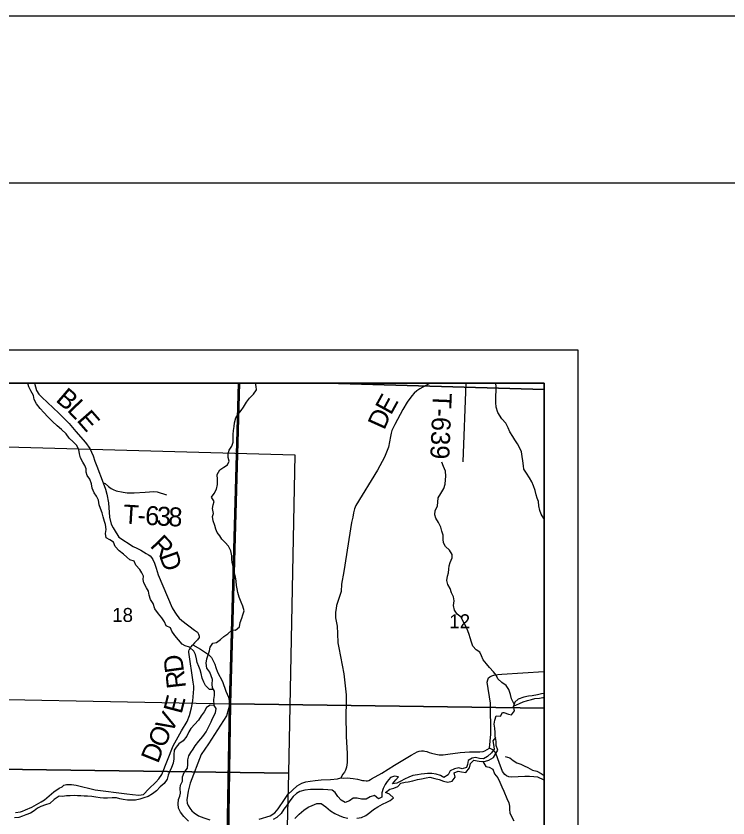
# Model space of a CAD drawing. Extents: x -19.9 to 41.9, y 0 to 32.3.
# Drawn here: x 7.317 to 9.45, y 19.598 to 22 of the extents above; entities that cross this region are included whole.
import ezdxf

# ---------------------------------------------------------------- set-up
doc = ezdxf.new("R2010")
doc.units = 0
for name, color, linetype in [('GM_X_Corporation', 7, 'Continuous'), ('GM_X_County_Road', 7, 'Continuous'), ('GM_X_County_Road_Text', 7, 'Continuous'), ('GM_X_Major_Lake', 7, 'Continuous'), ('GM_X_Major_River', 7, 'Continuous'), ('GM_X_Minor_River', 7, 'Continuous'), ('GM_X_Section', 7, 'Continuous'), ('GM_X_Section_Text', 7, 'Continuous'), ('GM_X_Township_Road', 7, 'Continuous'), ('GM_X_Township_Road_Text', 7, 'Continuous'), ('SH_Border', 7, 'Continuous'), ('SH_Cut_Line', 7, 'Continuous'), ('SH_Data', 7, 'Continuous')]:
    doc.layers.add(name, color=color, linetype=linetype)

msp = doc.modelspace()

# ---------------------------------------------------------------- linework, layer by layer
at = {"layer": 'GM_X_Corporation'}
for points in [[(8.9, 17.8974), (8.9, 20.9), (2.1, 20.9), (2.1, 17.918), (2.4715, 17.9106), (2.973, 17.9007), (3.7505, 17.884), (3.984, 17.879), (4.2613, 17.8672), (4.9169, 17.8392), (5.0192, 17.8403), (5.0257, 17.9637), (5.4954, 17.9559), (5.761, 17.9543), (5.9048, 17.9534), (6.2397, 17.9517), (6.2497, 17.9517), (6.3069, 17.9505), (6.7, 17.9422), (6.9468, 17.937), (7.3858, 17.9277), (7.5529, 17.9242), (7.9072, 17.9171)], [(7.9862, 20.9), (6.9594, 20.9), (6.9305, 19.9596), (7.9591, 19.9393)], [(8.9, 17.8974), (8.9, 20.9), (7.9833, 20.9), (7.9567, 19.9408), (7.9433, 19.1981), (7.9387, 18.9418), (7.9208, 18.3004), (7.9072, 17.9171)], [(8.2492, 20.9), (7.9862, 20.9), (7.9591, 19.9393), (8.9, 19.9267), (8.9, 20.8818)], [(8.9, 20.8818), (8.9, 20.9), (8.2492, 20.9)], [(7.9591, 19.9393), (7.944, 18.9426), (6.9135, 18.9637), (6.9305, 19.9596)], [(8.9, 18.9209), (8.9, 19.9267), (7.9591, 19.9393), (7.944, 18.9426)]]:
    msp.add_lwpolyline(points, close=True, dxfattribs=at)
msp.add_lwpolyline([(2.973, 17.9007), (3.7505, 17.884), (3.984, 17.879), (4.2613, 17.8672), (4.9169, 17.8392), (5.0192, 17.8403), (5.0257, 17.9637), (5.4954, 17.9559), (5.761, 17.9543), (5.9048, 17.9534), (6.2397, 17.9517), (6.2497, 17.9517), (6.3069, 17.9505), (6.7, 17.9422), (6.9468, 17.937), (7.3858, 17.9277), (7.5529, 17.9242), (7.9072, 17.9171), (7.9208, 18.3004), (7.9387, 18.9418), (7.9433, 19.1981), (7.9567, 19.9408), (7.9833, 20.9), (2.1, 20.9)], dxfattribs=at)
at = {"layer": 'GM_X_County_Road'}
for points in [[(7.3718, 20.9), (7.3775, 20.8787), (7.3846, 20.8678), (7.3944, 20.858), (7.4453, 20.8106), (7.4758, 20.7798), (7.4959, 20.7553), (7.5246, 20.7225), (7.5377, 20.7041), (7.5478, 20.6822), (7.5526, 20.667), (7.5588, 20.6514), (7.5775, 20.6016), (7.5849, 20.5825), (7.5887, 20.5678), (7.5933, 20.5419), (7.5968, 20.4993), (7.6017, 20.4776), (7.6074, 20.467), (7.6103, 20.4616), (7.6248, 20.4392), (7.668, 20.4112), (7.6784, 20.4056), (7.6911, 20.4005), (7.7069, 20.3901), (7.7141, 20.3861), (7.7182, 20.3827), (7.7225, 20.3783), (7.7268, 20.3718), (7.7321, 20.3615), (7.7366, 20.3457), (7.7423, 20.326), (7.7848, 20.2276), (7.7923, 20.2145), (7.7985, 20.2054), (7.8051, 20.1959), (7.8132, 20.1897), (7.8515, 20.1605), (7.8604, 20.1545), (7.8637, 20.1486), (7.8653, 20.1427), (7.8651, 20.1381), (7.8609, 20.1311), (7.852, 20.122)], [(7.852, 20.122), (7.8465, 20.1165), (7.8692, 20.1036), (7.8931, 20.0875), (7.9023, 20.0787), (7.9069, 20.0707), (7.9124, 20.0582), (7.9159, 20.0482), (7.9208, 20.0351), (7.9352, 20.0063), (7.9453, 19.9779), (7.9532, 19.9599), (7.9571, 19.9396), (7.9538, 19.9248), (7.9476, 19.9042), (7.8933, 19.8198), (7.8717, 19.7877), (7.8386, 19.7026), (7.8323, 19.6777), (7.829, 19.652), (7.8299, 19.6427), (7.8329, 19.635), (7.8373, 19.6271), (7.8437, 19.6191), (7.8507, 19.6128), (7.8632, 19.6045), (7.8792, 19.5982), (7.8977, 19.5919)], [(8.2899, 19.718), (8.2988, 19.7174), (8.3095, 19.7183), (8.3267, 19.7163), (8.3404, 19.7141), (8.3546, 19.7101), (8.3605, 19.7097), (8.3656, 19.7095), (8.3702, 19.7095), (8.3742, 19.7104), (8.3793, 19.7128), (8.3825, 19.7153), (8.4127, 19.7321), (8.451, 19.7557), (8.501, 19.7863), (8.5123, 19.7922), (8.5188, 19.796), (8.5252, 19.7984), (8.5319, 19.7992), (8.538, 19.7988), (8.5423, 19.798), (8.5477, 19.7967), (8.5548, 19.7939), (8.562, 19.7923), (8.5752, 19.7888), (8.5848, 19.7872), (8.5969, 19.7866), (8.6109, 19.7885), (8.6474, 19.7944), (8.6756, 19.796), (8.6965, 19.7963), (8.7072, 19.796), (8.7166, 19.7968), (8.722, 19.7989), (8.7359, 19.8073), (8.74, 19.8494), (8.7385, 19.9414), (8.729, 20.0043), (8.7302, 20.0112), (8.733, 20.0172), (8.7365, 20.0208), (8.7422, 20.0236), (8.7491, 20.0255), (8.7603, 20.0279), (8.7727, 20.0287), (8.8989, 20.0362), (8.9, 20.0363)], [(8.0453, 19.5943), (8.0783, 19.604), (8.0923, 19.6128), (8.1027, 19.6253), (8.1212, 19.6535), (8.1315, 19.6685), (8.1591, 19.6937), (8.1733, 19.7017), (8.1849, 19.7057), (8.1982, 19.7083), (8.2128, 19.7103), (8.2316, 19.7122), (8.2593, 19.7129), (8.28, 19.7156), (8.2899, 19.718)]]:
    msp.add_lwpolyline(points, dxfattribs=at)
at = {"layer": 'GM_X_Major_Lake'}
for points in [[(7.8022, 19.6402), (7.8039, 19.6531), (7.8075, 19.6627), (7.8093, 19.6722), (7.809, 19.6858), (7.81, 19.6957), (7.8159, 19.7083), (7.816, 19.7216), (7.8208, 19.7342), (7.8308, 19.7473), (7.8318, 19.7583), (7.8312, 19.7719), (7.8348, 19.7841), (7.8407, 19.7937), (7.8474, 19.8041), (7.854, 19.814), (7.8648, 19.8275), (7.8764, 19.8417), (7.886, 19.8555), (7.8912, 19.8655), (7.8963, 19.8758), (7.9019, 19.8862), (7.9059, 19.8961), (7.9143, 19.9133), (7.9168, 19.9255), (7.9102, 19.9352), (7.898, 19.9354), (7.8875, 19.9284), (7.8805, 19.9158), (7.8715, 19.9035), (7.8638, 19.8905), (7.8406, 19.8658), (7.8343, 19.8558), (7.8281, 19.8432), (7.8177, 19.8294), (7.8049, 19.82), (7.7963, 19.8104), (7.7904, 19.8008), (7.7891, 19.7868), (7.7893, 19.7746), (7.7872, 19.7617), (7.7829, 19.7487), (7.7763, 19.7361), (7.7726, 19.7262), (7.7698, 19.714), (7.7605, 19.7013), (7.7489, 19.6916), (7.7381, 19.6789), (7.7253, 19.67), (7.7125, 19.6618), (7.7, 19.6578), (7.6879, 19.6542), (7.675, 19.6517), (7.6511, 19.6513), (7.6381, 19.6534), (7.6282, 19.6555), (7.6179, 19.658), (7.605, 19.6585), (7.5909, 19.6575), (7.5791, 19.6573), (7.5689, 19.6579), (7.5563, 19.66), (7.5437, 19.6617), (7.5311, 19.663), (7.5213, 19.6636), (7.511, 19.6645), (7.5011, 19.6644), (7.4904, 19.6649), (7.479, 19.6644), (7.468, 19.6638), (7.4559, 19.6625), (7.4464, 19.6627), (7.4306, 19.6533), (7.4175, 19.6413), (7.4046, 19.6373), (7.3914, 19.6326), (7.3808, 19.6274), (7.3707, 19.6197), (7.3602, 19.6127), (7.3462, 19.6068), (7.3364, 19.6036), (7.3246, 19.5996), (7.3125, 19.5986)], [(8.3385, 19.5968), (8.3522, 19.5993), (8.3646, 19.6048), (8.3774, 19.6145), (8.3883, 19.6231), (8.4014, 19.6309), (8.4154, 19.6394), (8.4278, 19.6457), (8.4376, 19.6501), (8.4481, 19.6586), (8.4358, 19.6694), (8.4235, 19.6737), (8.4367, 19.6846), (8.4492, 19.6867), (8.4612, 19.6926), (8.4702, 19.7026), (8.4827, 19.7051), (8.4922, 19.706), (8.5058, 19.7092), (8.5198, 19.7129), (8.5319, 19.7154), (8.5459, 19.7186), (8.5573, 19.72), (8.5718, 19.716), (8.5852, 19.7132), (8.5982, 19.7085), (8.6108, 19.7049), (8.624, 19.7086), (8.633, 19.7197), (8.6297, 19.7326), (8.6422, 19.7385), (8.6517, 19.736), (8.6647, 19.7343), (8.6755, 19.7477), (8.6783, 19.7611), (8.6891, 19.7711), (8.6987, 19.769), (8.7109, 19.7669), (8.7234, 19.7683), (8.7332, 19.7715), (8.7475, 19.7789), (8.7549, 19.7912), (8.7605, 19.8008), (8.7561, 19.8147), (8.7555, 19.8268), (8.7538, 19.839)], [(8.7538, 19.839), (8.746, 19.829), (8.7473, 19.8176), (8.7498, 19.804), (8.7412, 19.7932), (8.7296, 19.782), (8.718, 19.775), (8.7058, 19.7763), (8.6939, 19.7792), (8.6833, 19.7775), (8.672, 19.7704), (8.67, 19.7583), (8.6663, 19.7487), (8.6535, 19.7451), (8.6439, 19.7476), (8.6306, 19.7455), (8.6182, 19.7392), (8.6116, 19.7266), (8.5988, 19.7191), (8.5884, 19.7247), (8.5754, 19.729), (8.5625, 19.7314), (8.5503, 19.7309), (8.5408, 19.7296), (8.5306, 19.7286), (8.5203, 19.7273)], [(8.4701, 19.7083), (8.4576, 19.7024), (8.4448, 19.7006), (8.4548, 19.7118), (8.4626, 19.7214), (8.4512, 19.7235), (8.4391, 19.7187), (8.4294, 19.7076), (8.4231, 19.698), (8.4169, 19.6858), (8.4125, 19.6728), (8.4127, 19.6603), (8.4025, 19.6555), (8.391, 19.6656), (8.3781, 19.6608), (8.3657, 19.6542), (8.3524, 19.6547), (8.3394, 19.6571), (8.3269, 19.6569), (8.3164, 19.6496), (8.3035, 19.644), (8.2916, 19.651), (8.2815, 19.6626), (8.2734, 19.6739), (8.2638, 19.6813), (8.2508, 19.6818), (8.2371, 19.6831), (8.2257, 19.6833), (8.2128, 19.6835), (8.1995, 19.6829), (8.1824, 19.6815), (8.1676, 19.6774), (8.1575, 19.6708), (8.1477, 19.6623), (8.1369, 19.6492), (8.1269, 19.6342), (8.1195, 19.6239), (8.111, 19.6116), (8.0982, 19.5992), (8.0869, 19.5937)], [(8.5203, 19.7273), (8.5063, 19.7248), (8.4938, 19.7204), (8.481, 19.7145), (8.4701, 19.7083)], [(7.8331, 19.5887), (7.8199, 19.6018), (7.8091, 19.6153), (7.8039, 19.6277), (7.8022, 19.6402)], [(8.1519, 19.5963), (8.1657, 19.6095), (8.1788, 19.6215), (8.192, 19.63), (8.2037, 19.6348), (8.2177, 19.6415), (8.231, 19.6409), (8.2452, 19.6309), (8.2587, 19.619), (8.2725, 19.6113), (8.2848, 19.605), (8.2974, 19.6007), (8.3111, 19.5971)]]:
    msp.add_lwpolyline(points, dxfattribs=at)
at = {"layer": 'GM_X_Major_River'}
for points in [[(8.9, 19.9703), (8.8911, 19.9694), (8.8791, 19.9665), (8.8636, 19.9638), (8.853, 19.9629), (8.8383, 19.9599), (8.8217, 19.9542), (8.8117, 19.9446), (8.8078, 19.9323)], [(8.8078, 19.9323), (8.8254, 19.9406), (8.8361, 19.9458), (8.8498, 19.9498), (8.8618, 19.9523), (8.8716, 19.9559), (8.8855, 19.9569), (8.8957, 19.9586), (8.9, 19.959)], [(8.7538, 19.839), (8.7522, 19.8408), (8.7528, 19.8537), (8.7518, 19.867), (8.7497, 19.8787), (8.7514, 19.8909), (8.7557, 19.9035), (8.769, 19.9033), (8.7749, 19.9137)], [(8.7749, 19.9137), (8.779, 19.9135), (8.7924, 19.9085), (8.8019, 19.9072), (8.8111, 19.9188), (8.8078, 19.9323)]]:
    msp.add_lwpolyline(points, dxfattribs=at)
at = {"layer": 'GM_X_Minor_River'}
for points in [[(7.9082, 19.983), (7.8967, 19.9826), (7.8848, 19.9947), (7.8791, 20.0045), (7.8744, 20.0166), (7.8716, 20.0302), (7.8685, 20.0419), (7.8646, 20.0518), (7.8599, 20.0635), (7.8572, 20.0741), (7.8544, 20.0873), (7.8494, 20.0979), (7.8367, 20.1092), (7.8238, 20.1136), (7.8142, 20.1185), (7.8035, 20.1313), (7.7927, 20.1448), (7.7839, 20.1573), (7.7792, 20.1675), (7.7667, 20.1731), (7.7612, 20.1855), (7.7535, 20.1972), (7.7432, 20.2093), (7.7328, 20.224), (7.7273, 20.2402), (7.72, 20.2527), (7.7161, 20.2652), (7.7137, 20.2773), (7.7075, 20.2871), (7.6994, 20.3018), (7.6974, 20.3117), (7.6985, 20.3219), (7.6939, 20.3318), (7.6873, 20.3423), (7.6758, 20.3551), (7.6708, 20.3672), (7.6582, 20.3709), (7.6486, 20.3792), (7.639, 20.3882), (7.626, 20.3983), (7.6138, 20.4107), (7.6087, 20.424), (7.598, 20.4311), (7.587, 20.4367), (7.5849, 20.4499), (7.5867, 20.4617), (7.5843, 20.4765), (7.5816, 20.4863), (7.5773, 20.4996), (7.5745, 20.512), (7.5698, 20.5245), (7.5659, 20.5355), (7.5635, 20.5495), (7.5577, 20.562), (7.5504, 20.5718), (7.5446, 20.5854), (7.5426, 20.599), (7.5383, 20.6123), (7.5298, 20.6236), (7.5267, 20.6334), (7.5266, 20.6433), (7.5224, 20.6535), (7.5166, 20.664), (7.51, 20.6765), (7.5072, 20.689), (7.5052, 20.7019), (7.4983, 20.7147), (7.4879, 20.7245), (7.4757, 20.7354), (7.4668, 20.7486), (7.4534, 20.7617), (7.4404, 20.7726), (7.4262, 20.7858), (7.4121, 20.7997), (7.3998, 20.8121), (7.3887, 20.8245), (7.3783, 20.8385), (7.3706, 20.8517), (7.3686, 20.8638), (7.3612, 20.8778), (7.3554, 20.8891), (7.3522, 20.9)], [(7.9102, 19.9352), (7.9091, 19.9531), (7.9113, 19.9649), (7.9116, 19.9778), (7.905, 19.988), (7.9049, 19.9986), (7.9052, 20.013), (7.9013, 20.0232), (7.8974, 20.0342), (7.8889, 20.047), (7.8862, 20.0611), (7.8883, 20.0747), (7.8928, 20.0861), (7.8961, 20.0987), (7.8986, 20.1093), (7.9069, 20.1212), (7.9171, 20.1232), (7.9292, 20.1327), (7.9398, 20.1419), (7.9519, 20.1496), (7.9647, 20.1611), (7.9745, 20.1604), (7.9859, 20.1708), (7.9884, 20.1837), (7.9932, 20.1966), (7.9965, 20.2065), (7.9999, 20.2187), (7.9959, 20.2327), (7.9909, 20.2448), (7.9855, 20.2592), (7.9812, 20.2728), (7.9792, 20.2842), (7.9779, 20.294), (7.9767, 20.3073), (7.9743, 20.3201), (7.9703, 20.336), (7.968, 20.3482), (7.9648, 20.3629), (7.9632, 20.3732), (7.9638, 20.3826), (7.9607, 20.3982), (7.953, 20.4118), (7.943, 20.4227), (7.9338, 20.4332), (7.9272, 20.443), (7.9199, 20.4532), (7.9157, 20.4634), (7.9121, 20.4736), (7.9075, 20.4884), (7.9058, 20.5005), (7.9084, 20.51), (7.9056, 20.5248), (7.907, 20.5354), (7.9104, 20.5461), (7.9023, 20.5589), (7.9109, 20.57), (7.9176, 20.5825), (7.9206, 20.597), (7.92, 20.6121), (7.9199, 20.6266), (7.927, 20.6403), (7.9398, 20.6491), (7.9508, 20.656), (7.9556, 20.6667), (7.9529, 20.6781), (7.9524, 20.6891), (7.9553, 20.7001), (7.9636, 20.7115), (7.9673, 20.7237), (7.9676, 20.7366), (7.9679, 20.7461), (7.9681, 20.759), (7.9707, 20.77), (7.9717, 20.781), (7.9758, 20.7962), (7.9833, 20.8088), (7.9911, 20.8187), (7.9986, 20.8287), (8.0069, 20.8435), (8.0166, 20.855), (8.0287, 20.8676), (8.0377, 20.8806), (8.0361, 20.8901), (8.0344, 20.9)], [(8.7604, 20.8121), (8.7553, 20.8288), (8.7544, 20.8424), (8.7543, 20.8549), (8.755, 20.8648), (8.756, 20.8754), (8.7559, 20.8895), (8.7547, 20.9)], [(8.9, 20.4933), (8.8982, 20.4954), (8.8908, 20.5077), (8.8868, 20.5187), (8.8839, 20.533), (8.8822, 20.5455), (8.879, 20.5557), (8.8754, 20.5658), (8.8725, 20.5787), (8.8678, 20.5923), (8.8622, 20.6047), (8.8556, 20.6171), (8.8466, 20.6309), (8.8389, 20.6429), (8.8372, 20.6528), (8.8358, 20.6675), (8.8337, 20.6811), (8.8315, 20.6944), (8.8256, 20.7075), (8.8201, 20.7188), (8.8112, 20.7308), (8.8061, 20.7405), (8.7968, 20.7544), (8.7917, 20.7668), (8.7843, 20.7803), (8.7727, 20.793), (8.7604, 20.8121)], [(8.7728, 20.0039), (8.7606, 20.0151), (8.7555, 20.0257), (8.7475, 20.0359), (8.7356, 20.0491), (8.7271, 20.0592), (8.7168, 20.072), (8.7117, 20.0838), (8.7063, 20.0947), (8.696, 20.1011), (8.686, 20.1127), (8.6814, 20.1248), (8.6778, 20.1373), (8.6751, 20.1472), (8.6712, 20.1585), (8.6661, 20.1706), (8.6573, 20.1846), (8.6507, 20.1997), (8.6392, 20.2087), (8.6304, 20.2208), (8.6276, 20.2348), (8.6298, 20.2481), (8.6277, 20.2602), (8.6216, 20.2719), (8.6176, 20.2851), (8.6111, 20.2972), (8.6079, 20.3089), (8.6101, 20.3222), (8.6127, 20.3317), (8.6137, 20.3431), (8.6148, 20.3534), (8.6173, 20.3629), (8.6237, 20.3766), (8.624, 20.3868), (8.6159, 20.4001), (8.604, 20.4106), (8.5978, 20.4223), (8.5966, 20.4329), (8.5965, 20.4454), (8.5933, 20.4568), (8.5898, 20.4693), (8.5825, 20.4832), (8.5744, 20.4957), (8.572, 20.5059), (8.573, 20.5192), (8.5798, 20.5321), (8.5818, 20.5572), (8.5901, 20.5702), (8.5991, 20.5843), (8.6027, 20.5976), (8.6034, 20.6109), (8.6048, 20.6215), (8.6043, 20.6367), (8.5981, 20.6503), (8.593, 20.6639)], [(8.8098, 19.9386), (8.8015, 19.9551), (8.7987, 19.9679), (8.7935, 19.9826), (8.7853, 19.995), (8.7728, 20.0039)], [(8.7829, 19.7823), (8.7963, 19.7776), (8.807, 19.7698), (8.8177, 19.7635), (8.8292, 19.7588), (8.8398, 19.754), (8.8509, 19.7493), (8.8647, 19.7412), (8.878, 19.7376), (8.891, 19.731), (8.9, 19.7253)], [(8.716, 19.7675), (8.7249, 19.7523), (8.7344, 19.7497), (8.7455, 19.7438), (8.7505, 19.7305), (8.7605, 19.7177), (8.7667, 19.7056), (8.7729, 19.6909), (8.7783, 19.678)], [(8.7783, 19.678), (8.7874, 19.6565), (8.7937, 19.6433), (8.7957, 19.6335), (8.7959, 19.6233), (8.7968, 19.6134), (8.8031, 19.5999), (8.8082, 19.5893)]]:
    msp.add_lwpolyline(points, dxfattribs=at)
at = {"layer": 'GM_X_Section'}
for points in [[(7.1444, 20.7139), (8.1526, 20.6857), (8.1335, 19.7322), (7.1171, 19.7458)], [(7.1171, 19.7458), (8.1335, 19.7322), (8.1079, 18.7263), (7.1021, 18.7492)]]:
    msp.add_lwpolyline(points, close=True, dxfattribs=at)
at = {"layer": 'GM_X_Township_Road'}
msp.add_line((8.665, 20.9), (8.6553, 20.6648), dxfattribs=at)
for points in [[(8.5566, 20.9), (8.5559, 20.8996), (8.5269, 20.8834), (8.5177, 20.8776), (8.5096, 20.8708), (8.5026, 20.8626), (8.4892, 20.8434), (8.4756, 20.8214), (8.4523, 20.7764), (8.4481, 20.7685), (8.4432, 20.7581), (8.4422, 20.7541)], [(8.4422, 20.7541), (8.4411, 20.7502), (8.4389, 20.7406), (8.4359, 20.7248), (8.4327, 20.7085), (8.4209, 20.6785), (8.4003, 20.6398), (8.3352, 20.534), (8.3313, 20.5241), (8.3279, 20.5119), (8.326, 20.4994), (8.3223, 20.4832), (8.2991, 20.3365), (8.2926, 20.2985), (8.291, 20.2758), (8.2773, 20.2346), (8.2757, 20.2257), (8.2744, 20.2142), (8.2744, 20.1976), (8.2788, 20.1723), (8.2805, 20.1505), (8.2815, 20.1229), (8.2845, 20.1071), (8.2995, 20.0298), (8.3059, 19.9669), (8.3065, 19.9415), (8.305, 19.9068), (8.3062, 19.8421), (8.3088, 19.7914), (8.309, 19.7638), (8.3073, 19.7501), (8.304, 19.7414), (8.3006, 19.7353), (8.2957, 19.7289), (8.2899, 19.718)], [(7.5775, 20.6016), (7.5835, 20.5993), (7.5934, 20.5909), (7.6015, 20.5843), (7.6075, 20.5816), (7.6169, 20.5781), (7.6381, 20.5737), (7.6502, 20.5723), (7.6702, 20.5721), (7.7032, 20.5742), (7.7166, 20.575), (7.7287, 20.5755), (7.7398, 20.5745), (7.7677, 20.5659)], [(7.315, 19.6147), (7.3299, 19.6167), (7.3357, 19.6187), (7.3451, 19.6224), (7.3643, 19.6306), (7.3919, 19.6459), (7.402, 19.6518), (7.4302, 19.6766), (7.4455, 19.687), (7.4547, 19.6915), (7.4598, 19.6964), (7.4682, 19.6985), (7.4832, 19.6985), (7.4972, 19.6964), (7.5537, 19.6817), (7.6486, 19.6702), (7.6654, 19.6681), (7.6851, 19.6666), (7.6982, 19.6685), (7.7143, 19.6851), (7.7356, 19.7052), (7.7446, 19.7149), (7.7539, 19.7283), (7.7874, 19.8144), (7.8122, 19.8593), (7.8292, 19.887), (7.8369, 19.9046), (7.843, 19.9279), (7.8464, 19.9484), (7.8491, 19.9848), (7.8491, 19.9922), (7.8477, 20.0043), (7.8345, 20.0947), (7.8346, 20.0979), (7.8356, 20.1012), (7.8365, 20.1029), (7.8405, 20.1098), (7.8465, 20.1165)], [(8.9, 19.7107), (8.8803, 19.7197), (8.8688, 19.7216), (8.8558, 19.7222), (8.842, 19.7226), (8.8018, 19.72), (8.7932, 19.7214), (8.7864, 19.7243), (8.7814, 19.7282), (8.7748, 19.7368), (8.7644, 19.7643), (8.7557, 19.7893), (8.7517, 19.7955), (8.7454, 19.8015), (8.7359, 19.8073)]]:
    msp.add_lwpolyline(points, dxfattribs=at)
at = {"layer": 'SH_Border'}
msp.add_lwpolyline([(1.5, 21.5), (33.5, 21.5), (33.5, 0.5), (1.5, 0.5)], close=True, dxfattribs=at)
at = {"layer": 'SH_Cut_Line'}
msp.add_lwpolyline([(0, 0), (34, 0), (34, 22), (0, 22)], close=True, dxfattribs=at)
at = {"layer": 'SH_Data'}
for p, q in [((2, 21), (9, 21)), ((9, 21), (9, 14)), ((2.1, 20.9), (8.9, 20.9)), ((8.9, 20.9), (8.9, 14.1))]:
    msp.add_line(p, q, dxfattribs=at)

# ---------------------------------------------------------------- texts
at = {"layer": 'GM_X_County_Road_Text'}
for s, rotation, p in [('B', 319.314, (7.4329, 20.8478)), ('L', 314.25, (7.4673, 20.8183)), ('E', 311.1577, (7.4964, 20.7884)), ('R', 314.1265, (7.7161, 20.4116)), ('D', 289.4522, (7.7452, 20.3836))]:
    msp.add_text(s, height=0.0568, rotation=rotation, dxfattribs=at).set_placement(p)
at = {"layer": 'GM_X_Section_Text'}
for s, p in [('18', (7.6049, 20.185)), ('12', (8.6153, 20.1662))]:
    msp.add_text(s, height=0.04186, rotation=0, dxfattribs=at).set_placement(p)
at = {"layer": 'GM_X_Township_Road_Text'}
for s, height, rotation, p in [('E', 0.0568, 61.2715, (8.4403, 20.8024)), ('T-639', 0.05682, 267.6418, (8.5662, 20.8718)), ('D', 0.0568, 65.7619, (8.4202, 20.7578)), ('T', 0.0568, 356.4347, (7.6366, 20.4803)), ('6', 0.0568, 356.8827, (7.7025, 20.4763)), ('3', 0.0568, 356.8927, (7.7372, 20.4744)), ('8', 0.0568, 356.8927, (7.7718, 20.4726)), ('-', 0.0568, 356.8312, (7.6793, 20.4776)), ('D', 0.0568, 97.8658, (7.8206, 20.0365)), ('R', 0.0568, 96.4985, (7.8261, 19.9887)), ('E', 0.0568, 75.395, (7.8126, 19.9074)), ('V', 0.0568, 59.6985, (7.7809, 19.8486)), ('O', 0.0568, 64.6789, (7.7602, 19.8045)), ('D', 0.0568, 68.2513, (7.742, 19.7589))]:
    msp.add_text(s, height=height, rotation=rotation, dxfattribs=at).set_placement(p)

doc.saveas('drawing.dxf')
